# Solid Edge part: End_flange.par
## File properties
Author: jmrobins
Template: Ansimm.Par
Last saved by: rkriggs
Revision: 62
Application: Solid Edge
Density: 0.00000847 kg/mm^3
Accuracy: 0.99
Material: Brass, yellow brass
Face Style: Brass
Fill Style: ANSI33(Brass)
Virtual Style: Polished brass
Coef. of Thermal Exp: 2e-05
Thermal Conductivity: 116.0
Specific Heat: 377.0
Modulus of Elasticity: 103421355000.0
Poission's Ratio: 0.32
Yield Stress: 413685420.0
Ultimate Stress: 510212018.0
Elongation: 0.0
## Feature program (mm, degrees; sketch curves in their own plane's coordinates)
pattern "unnamed Pattern 1"
pattern "unnamed Pattern 2"
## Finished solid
Body 1: solid body, 56 faces, 118 edges, 60 vertices.
  Faces by surface: cylinder 28, plane 16, torus 10, cone 1, sphere 1
  Edges by curve: circle 62, line 44, intersection 12
Bounding box of the edges (mm; curved faces can reach further): 90.000 x 90.000 x 50.000, from (-45, -45, -20) to (45, 45, 30).
Cylindrical faces by radius (mm): R1.5 x12, R2 x4, R5 x4, R10 x4, R15 x1, R25 x1, R27.5 x1, R32.5 x1
Conical faces (half-angle, radius in mm at the cone's reference point): 70 deg R32.25 x1
Toroidal faces (ring radius, tube radius in mm): R3 r1.5 x6, R8 r2 x4
Spherical faces by radius (mm): R30 x1
Planar faces by outward normal: +x 1, +y 2, +z 3, -x 1, -y 2, -z 3, oblique 4
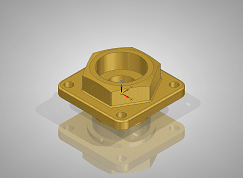
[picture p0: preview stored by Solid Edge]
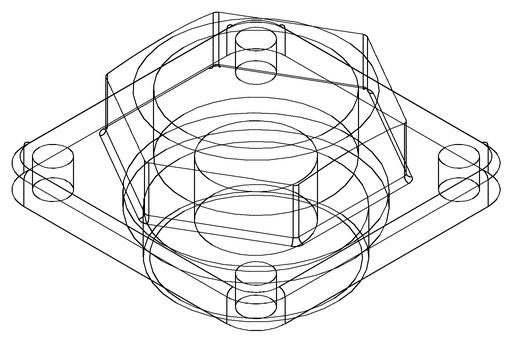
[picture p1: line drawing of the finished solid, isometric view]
